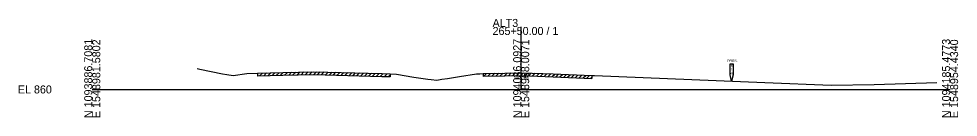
# Model space of a CAD drawing. Extents: x -26 to 1303, y -10 to 19582.
# Drawn here: x 974.3 to 1302.8, y 18990.3 to 19024.7 of the extents above; entities that cross this region are included whole.
import ezdxf

# ---------------------------------------------------------------- set-up
doc = ezdxf.new("R2010")
doc.units = 0
for name, color, linetype in [('Default', 7, 'Continuous'), ('RD_GPK_XS_Cell', 7, 'Continuous'), ('RD_XS_ExGround', 7, 'Continuous'), ('RD_XS_ExPaveRet', 7, 'Continuous'), ('RD_XS_ExRW', 7, 'Continuous'), ('RD_XS_TX_Elev_EX', 7, 'Continuous')]:
    doc.layers.add(name, color=color, linetype=linetype)

msp = doc.modelspace()

# ---------------------------------------------------------------- linework, layer by layer
at = {"layer": 'RD_GPK_XS_Cell'}
for p, q in [((1150, 19000), (1150, 19021.83)), ((1000, 19000), (1150, 19000)), ((1150, 19000), (1300, 19000))]:
    msp.add_line(p, q, dxfattribs=at)
at = {"layer": 'RD_XS_ExGround'}
msp.add_lwpolyline([(1036.66, 19007.28), (1037.66, 19007.13), (1045.53, 19005.5), (1047.11, 19005.21), (1049.3, 19004.88), (1054.03, 19005.54), (1057.82, 19005.66), (1066.61, 19005.9), (1077.47, 19006.21), (1101.26, 19005.53), (1104.18, 19005.46), (1106.4, 19005.35), (1112.48, 19004.29), (1117.36, 19003.55), (1118.52, 19003.49), (1120.45, 19003.27), (1122.26, 19003.6), (1124.25, 19003.87), (1128.39, 19004.47), (1134.36, 19005.43), (1135.49, 19005.47), (1136.71, 19005.54), (1144.28, 19005.72), (1150.15, 19005.82), (1161.23, 19005.41), (1174.73, 19004.83), (1175.68, 19004.85), (1235.25, 19002.43), (1258.38, 19001.47), (1273.4, 19001.71), (1295.33, 19002.37)], dxfattribs=at)
at = {"layer": 'RD_XS_ExPaveRet'}
for p, q in [((1057.82, 19005.44), (1058.05, 19005.67)), ((1057.82, 19005.66), (1057.82, 19004.66)), ((1058.53, 19004.73), (1059.5, 19005.71)), ((1059.98, 19004.77), (1060.96, 19005.75)), ((1061.43, 19004.81), (1062.41, 19005.79)), ((1062.89, 19004.85), (1063.86, 19005.83)), ((1064.34, 19004.89), (1065.32, 19005.86)), ((1065.79, 19004.93), (1066.77, 19005.9)), ((1067.25, 19004.97), (1068.23, 19005.95)), ((1068.7, 19005.01), (1069.68, 19005.99)), ((1070.16, 19005.05), (1071.14, 19006.03)), ((1071.62, 19005.09), (1072.59, 19006.07)), ((1073.07, 19005.14), (1074.05, 19006.11)), ((1074.53, 19005.18), (1075.51, 19006.16)), ((1075.98, 19005.22), (1076.96, 19006.2)), ((1077.44, 19005.26), (1078.37, 19006.19)), ((1078.82, 19005.22), (1079.74, 19006.15)), ((1080.19, 19005.18), (1081.12, 19006.11)), ((1081.57, 19005.14), (1082.49, 19006.07)), ((1082.94, 19005.11), (1083.87, 19006.03)), ((1084.32, 19005.07), (1085.24, 19005.99)), ((1085.69, 19005.03), (1086.61, 19005.95)), ((1087.07, 19004.99), (1087.99, 19005.91)), ((1088.44, 19004.95), (1089.36, 19005.87)), ((1089.82, 19004.91), (1090.74, 19005.83)), ((1091.19, 19004.87), (1092.11, 19005.79)), ((1092.57, 19004.83), (1093.49, 19005.75)), ((1093.94, 19004.79), (1094.86, 19005.71)), ((1095.32, 19004.75), (1096.24, 19005.67)), ((1096.69, 19004.71), (1097.61, 19005.64)), ((1139.79, 19004.66), (1140.77, 19005.64)), ((1141.24, 19004.7), (1142.21, 19005.67)), ((1142.69, 19004.73), (1143.66, 19005.7)), ((1144.14, 19004.76), (1145.1, 19005.73)), ((1145.58, 19004.79), (1146.54, 19005.76)), ((1147.01, 19004.81), (1147.98, 19005.78)), ((1148.45, 19004.84), (1149.42, 19005.81)), ((1149.89, 19004.86), (1150.82, 19005.79)), ((1151.27, 19004.83), (1152.19, 19005.74)), ((1152.63, 19004.78), (1153.55, 19005.69)), ((1154, 19004.73), (1154.91, 19005.64)), ((1098.06, 19004.67), (1098.99, 19005.6)), ((1099.44, 19004.63), (1100.36, 19005.56)), ((1100.81, 19004.59), (1101.74, 19005.52)), ((1102.19, 19004.56), (1103.12, 19005.48)), ((1103.57, 19004.52), (1104.18, 19005.13)), ((1104.18, 19005.46), (1104.18, 19004.46)), ((1136.71, 19005.54), (1136.71, 19004.54)), ((1136.9, 19004.6), (1137.87, 19005.57)), ((1138.35, 19004.63), (1139.32, 19005.6)), ((1155.36, 19004.68), (1156.28, 19005.59)), ((1156.73, 19004.63), (1157.64, 19005.54)), ((1158.09, 19004.57), (1159.01, 19005.49)), ((1159.45, 19004.52), (1160.37, 19005.44)), ((1160.82, 19004.47), (1161.73, 19005.39)), ((1162.18, 19004.42), (1163.09, 19005.33)), ((1163.53, 19004.36), (1164.44, 19005.27)), ((1164.89, 19004.3), (1165.8, 19005.21)), ((1166.24, 19004.24), (1167.15, 19005.16)), ((1167.6, 19004.19), (1168.51, 19005.1)), ((1168.96, 19004.13), (1169.87, 19005.04)), ((1170.31, 19004.07), (1171.22, 19004.98)), ((1171.67, 19004.01), (1172.58, 19004.92)), ((1173.02, 19003.95), (1173.94, 19004.86)), ((1174.38, 19003.9), (1174.73, 19004.25)), ((1174.73, 19004.83), (1174.73, 19003.83))]:
    msp.add_line(p, q, dxfattribs=at)
for points in [[(1057.82, 19004.71), (1066.61, 19004.95), (1077.47, 19005.26), (1101.26, 19004.58), (1104.18, 19004.51)], [(1136.71, 19004.59), (1144.28, 19004.77), (1150.15, 19004.87), (1161.23, 19004.46), (1174.73, 19003.88)]]:
    msp.add_lwpolyline(points, dxfattribs=at)
at = {"layer": 'RD_XS_ExRW'}
msp.add_lwpolyline([(1223.04, 19008.92), (1224.14, 19008.92), (1224.14, 19005.1), (1223.59, 19002.91), (1223.04, 19005.1)], close=True, dxfattribs=at)

# ---------------------------------------------------------------- texts
at = {"layer": 'Default'}
msp.add_text('-', height=0.0001, dxfattribs=at).set_placement((1000, 19000))
at = {"layer": 'RD_GPK_XS_Cell'}
for s, p in [('ALT3', (1140, 19021.83)), ('265+50.00 / 1', (1140, 19019.03)), ('EL 860', (974, 18998.6))]:
    msp.add_text(s, height=2.8, dxfattribs=at).set_placement(p)
for s, p in [('N 1093886.7081', (1000, 18990)), ('E 1548981.5802', (1002.8, 18990)), ('N 1094036.0927', (1150, 18990)), ('E 1548968.0071', (1152.8, 18990)), ('N 1094185.4773', (1300, 18990)), ('E 1548954.4340', (1302.8, 18990))]:
    msp.add_text(s, height=2.8, rotation=90, dxfattribs=at).set_placement(p)
at = {"layer": 'RD_XS_ExRW'}
for s, p in [('PRES.', (1222.04, 19009.55)), ('W', (1223.12, 19005.21)), ('R', (1223.3, 19007.83)), ('/', (1223.42, 19006.52))]:
    msp.add_text(s, height=0.875, dxfattribs=at).set_placement(p)
at = {"layer": 'RD_XS_TX_Elev_EX'}
msp.add_text('865.81', height=1.25, dxfattribs=at).set_placement((1147.56, 19003.39))

doc.saveas('drawing.dxf')
